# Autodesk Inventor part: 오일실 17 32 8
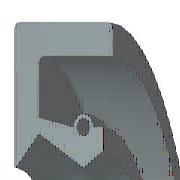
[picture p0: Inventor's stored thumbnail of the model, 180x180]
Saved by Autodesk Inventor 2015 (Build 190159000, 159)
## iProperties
IsCustomPart: 1
Created: 2012-02
Part Number: 오일실 17 32 8
Material: 고무
Description: 오일-실
Document SubType Name: Modeling
Standard: KS B 2804
Designer: mduedu
Standards Organization: KS
Language: ko-KR
Size Designation: D - 17 32 8
Categories: <MemberInstance><Categories><Category DisplayName="샤프트 부품" InternalName="7f7aeb1f-a693-4053-b835-cee3144e0d98" Mnemonic="SHFT"><Category DisplayName="실링" Intern
Density: 0.93 g/cm^3
Mass: 2.28027 g
Surface Area: 32.1224 cm^2
Volume: 2.45191 cm^3
Appearance: 고무 - 검은색 - 버전 1.1
Author: mduedu
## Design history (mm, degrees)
revolve "본체" stored, may be unused: angle "d17" = 90 deg
revolve "스프링1" stored, may be unused: angle "d18" = 90 deg
body "Solid1"
sketch "스케치1"
  geometry: L1 (0, 16)-(8, 16); L2 (8, 14.25)-(1.75, 14.25); L3 (1.75, 10.25)-(4.9, 8.5); L4 (4.9, 8.5)-(0, 8.5); L5 (0, 0)-(9.586, 0) reference; L6 (4.9, 8.5)-(6.3, 9.375); L7 (0, 18)-(0, -3) reference; L8 (-1.941, 0)-(11.507, 0) reference; L9 (4.2, 10.6)-(1.75, 11.21); L10 (1.75, 11.21)-(1.75, 14.25); L11 (0, 16)-(0, 8.588); L12 (4.9, 8.5)-(0, 8.5); L13 (1.75, 10.25)-(0.152, 8.528); L14 (8, 16)-(8, 14.25); L15 (5.6, 10.6)-(6.3, 10.6); L16 (6.3, 10.6)-(6.3, 9.375); C1 r 0.455 at (4.9, 10.6); A1 r 0.7 centre (4.9, 10.6) between (5.6, 10.6) and (4.2, 10.6); A2 r 0.088 centre (0.088, 8.588) between (0, 8.588) and (0.152, 8.528); 1 further point
  constraints: 28 end point, 5 horizontal alignment, 5 point on line, 4 point on circle, 4 vertical alignment, 3 centre point, 3 tangent, 2 collinear, 2 horizontal, 2 perpendicular, 1 coincident, 1 parallel
  dimensions: "d0" = 32 diameter of L1 L5 (= SD2); "d1" = 1.75 distance of L1.end L2.start (= SD); "d2" = 0.91 diameter of C1 (= SPDI); "d3" = 1.4 diameter of A1 (= SPDA); "d4" = 17 diameter of L3.end L5 (= NND); "d5" = 20.5 diameter of L3.start L5 (= TKDM); "d7" = 22.42 diameter of L9.end L5 (= TKDM + 0.24 x SWDT); "d8" = 1.75 distance between parallel lines of L11 L10 (= SD); "d9" = 4.9 distance from line of L11 C1.centre (= SPDST); "d10" = 21.2 diameter of C1.centre L5 (= HLDM); "d11" = 0.0875 radius of A2 (= 0.25 x LAB); "d12" = 6.3 distance between parallel lines of L11 L16 (= SDI); "d13" = 18.75 diameter of L6.end L5 (= ABDM); "d14" = 8 distance from line of L11 L1.end (= SWDT)
fillet "모깎기1" dims "d6" = 0.3 (= RR)
other parameters: "SD2" = 32 [user parameter; used in 1 equation term], "SWDT" = 8 [user parameter; used in 2 equation terms], "RR" = 0.3 [user parameter; used in 1 equation term], "SD" = 1.75 [user parameter; used in 2 equation terms], "NND" = 17 [user parameter; used in 1 equation term], "SPDA" = 1.4 [user parameter; used in 1 equation term], "SPDI" = 0.91 [user parameter; used in 1 equation term], "TKDM" = 20.5 [user parameter; used in 2 equation terms], "HLDM" = 21.2 [user parameter; used in 1 equation term], "ABDM" = 18.75 [user parameter; used in 1 equation term], "SDI" = 6.3 [user parameter; used in 1 equation term], "SPDST" = 4.9 [user parameter; used in 1 equation term], "LAB" = 0.35 [user parameter; used in 1 equation term], "d15" = 0, "d16" = 0, "d19" = 0
